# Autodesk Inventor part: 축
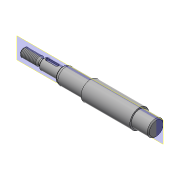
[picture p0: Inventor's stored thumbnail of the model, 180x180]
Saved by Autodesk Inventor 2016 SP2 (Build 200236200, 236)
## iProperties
Created: 2015-11
Part Number: 축
Material: 강철, 연강
Document SubType Name: Modeling
Designer: mduedu
Density: 1 g/cm^3
Appearance: 강철
Author: mduedu
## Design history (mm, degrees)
sketch "스케치1"
  geometry: L1 (-86, 0)-(86, 0); L2 (-86, 0)-(-86, 4); L3 (-86, 4)-(-70.732, 4); L4 (-70.732, 4)-(-69, 3); L5 (-69, 3)-(-67, 3); L6 (-67, 3)-(-67, 5); L7 (-67, 5)-(-49, 5); L8 (-49, 5)-(-49, 6.55); L9 (-47.355, 7.5)-(-23, 7.5); L10 (-23, 7.5)-(-23, 9); L11 (0, 0)-(0, 9); L12 (86, 4)-(70.732, 4); L13 (70.732, 4)-(69, 3); L14 (69, 3)-(67, 3); L15 (67, 3)-(67, 5); L16 (67, 5)-(49, 5); L17 (23, 7.5)-(23, 9); L18 (86, 0)-(86, 4); L19 (-23, 9)-(23, 9); L20 (-49, 6.55)-(-47.355, 7.5); L21 (47.355, 7.5)-(23, 7.5); L22 (49, 6.55)-(47.355, 7.5); L23 (49, 5)-(49, 6.55); 1 further point
  constraints: 46 end point, 10 symmetric about line, 6 perpendicular, 5 parallel, 2 midpoint, 1 coincident, 1 horizontal
  dimensions: "d0" = 172 distance of L1.start L1.end (derived); "d1" = 8 diameter of L3 L1; "d2" = 30 deg angle of L4 L5; "d3" = 6 diameter of L5 L1; "d4" = 10 diameter of L7 L1; "d5" = 15 diameter of L9 L1; "d6" = 18 diameter of L19 L1; "d8" = 18 distance of L6.end L7.end; "d9" = 46 distance of L10.end L17.end; "d10" = 2 distance of L4.end L5.end; "d11" = 17 distance from line of L4.end L2; "d16" = 13.1 diameter of L8.end L1; "d17" = 30 deg angle of L20 L9; "d18" = 26 distance between parallel lines of L10 L8
revolve "회전1" sketch "스케치1" stored, may be unused: angle "d12" = 90 deg
chamfer "모따기1" distance "d13" = 1; stored, may be unused: second distance "d14" = 2, angle "d15" = 45 deg
fillet "모깎기1" dims "d19" = 4, "d20" = 0.5
node "작업 평면1"
sketch "스케치2" dims "d23" = 12
  geometry: L1 (-5.5, 1.5)-(3.5, 1.5); L2 (3.5, 1.5)-(3.5, -1.5); L3 (3.5, -1.5)-(-5.5, -1.5); L4 (-5.5, -1.5)-(-5.5, 1.5); L5 (-9, -4)-(-9, 4) reference; 3 further points
  constraints: 8 end point, 2 midpoint, 2 parallel, 2 vertical alignment, 1 horizontal, 1 perpendicular, 4 other
  dimensions: "d21" = 3 distance between parallel lines of L3 L1; "d24" = 2 dimension on L5
extrude "돌출1" cut sketch "스케치2" distance "d25" = 1.8; taper "d26" = 0 deg
feature "스레드1" dims "d27" = 10, "d28" = 0
feature "스레드2" dims "d29" = 10, "d30" = 0
chamfer "모따기2" distance "d31" = 1; stored, may be unused: second distance "d32" = 2, angle "d33" = 45 deg
node "작업 평면2"
sketch "스케치3"
  geometry: C1 r 7.5 at (0, 0) reference; 1 further point
extrude "돌출2" cut sketch "스케치3" stored distance "d36" = 10; taper "d37" = 0 deg
chamfer "모따기3" distance "d38" = 1; stored, may be unused: second distance "d39" = 2, angle "d40" = 45 deg
node "솔리드1"
mirror "대칭1"
node "절단 모서리 투영1"
other parameters: "d35" = 16
